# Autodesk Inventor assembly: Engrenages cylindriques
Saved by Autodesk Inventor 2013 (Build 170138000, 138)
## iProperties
Created: 2011-10
Part Number: Engrenages cylindriques
Document SubType Name: Assembly
Designer: Laur
ClientObjectVersion: 1
Author: Laur
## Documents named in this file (2)
- D:\_an13-14\FORMULAIRE_2014\Sujet E4 Poissy 2014\Modélisation_7970_shimano_2014\arbre moteur et pignon 11 dents m0,25\Design Accelerator\Engrenages cylindriques1.iam
- D:\_an13-14\FORMULAIRE_2014\Sujet E4 Poissy 2014\Modélisation_7970_shimano_2014\arbre moteur et pignon 11 dents m0,25\Design Accelerator\Engrenage cylindrique11.ipt
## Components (1 placed, 1 different names)
1. Engrenage cylindrique1:1
